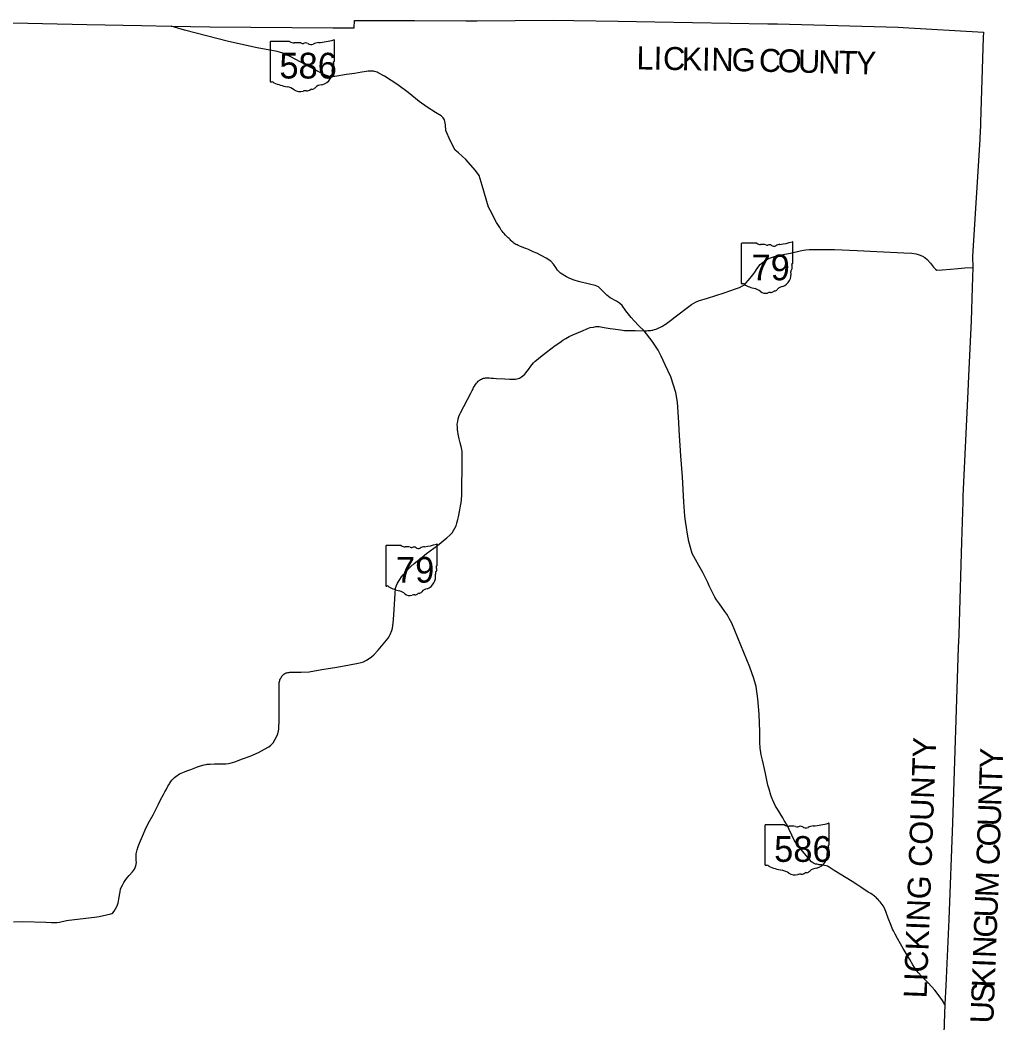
# Model space of a CAD drawing. Extents: x 1853412 to 2125412, y 679418 to 855418.
# Drawn here: x 2015090 to 2057872, y 772335 to 816009 of the extents above; entities that cross this region are included whole.
import ezdxf

# ---------------------------------------------------------------- set-up
doc = ezdxf.new("R2010")
doc.units = 0
for name, color, linetype in [('GM_X_County', 7, 'Continuous'), ('GM_X_County_Text', 7, 'Continuous'), ('GM_X_State_Location', 7, 'Continuous'), ('GM_X_State_Route', 7, 'Continuous'), ('GM_X_State_Shield', 7, 'Continuous')]:
    doc.layers.add(name, color=color, linetype=linetype)

msp = doc.modelspace()

# ---------------------------------------------------------------- linework, layer by layer
at = {"layer": 'GM_X_County'}
msp.add_lwpolyline([(2014115, 815904), (2017998, 815808), (2020382, 815768), (2021673, 815746), (2023355, 815717), (2028708, 815664), (2029367, 815674), (2029630, 815668), (2029642, 815987), (2032252, 815993), (2034492, 815973), (2034983, 815969), (2038297, 816009), (2039196, 815994), (2041129, 815964), (2042723, 815938), (2047645, 815846), (2048065, 815838), (2053316, 815692), (2053523, 815687), (2057031, 815485), (2057019, 815250), (2056899, 811568), (2056897, 811400), (2056861, 810899), (2056861, 810876), (2056863, 810840), (2056867, 810805), (2056541, 805722), (2056567, 805237), (2056538, 804363), (2056484, 802909), (2056380, 800498), (2056351, 799840), (2056130, 795281), (2056125, 795083), (2056131, 795035), (2056068, 793283), (2055973, 789772), (2055957, 789237), (2055919, 788685), (2055674, 781043), (2055513, 776843), (2055388, 773963), (2055343, 773147), (2055023, 763820)], dxfattribs=at)
at = {"layer": 'GM_X_State_Route'}
for points in [[(2029654, 813686), (2029302, 813633), (2028789, 813552), (2028645, 813551), (2028515, 813560), (2028381, 813609), (2028126, 813739), (2027312, 814168), (2026847, 814423), (2026534, 814571), (2026283, 814638), (2025407, 814794), (2024156, 815073), (2022247, 815574), (2021674, 815743)], [(2046067, 789739), (2045962, 789941), (2045911, 790035), (2045852, 790135), (2045772, 790255), (2045534, 790586), (2045403, 790755), (2045335, 790870), (2045246, 791045), (2045088, 791370), (2045024, 791509), (2044809, 791947), (2044629, 792250), (2044344, 792785), (2044203, 793304), (2044137, 793614), (2044092, 793908), (2044057, 794188), (2044031, 794403), (2043985, 795011), (2043927, 796116), (2043856, 797033), (2043783, 798155), (2043764, 798487), (2043700, 799371), (2043637, 799784), (2043413, 800466), (2043167, 801000), (2042996, 801365), (2042862, 801635), (2042599, 802028), (2042258, 802474), (2042021, 802691), (2041816, 802905), (2041692, 803051), (2041456, 803345), (2041293, 803579), (2041189, 803673), (2041048, 803761), (2040783, 803909), (2040632, 804030), (2040354, 804308), (2040267, 804394), (2040116, 804455), (2039873, 804513), (2039404, 804623), (2039204, 804675), (2039026, 804758), (2038880, 804823), (2038621, 804990), (2038489, 805117), (2038405, 805228), (2038314, 805373), (2038192, 805506), (2037995, 805646), (2037588, 805856), (2037420, 805914), (2037310, 805968), (2037219, 806010), (2037143, 806046), (2037055, 806079), (2036941, 806125), (2036843, 806162), (2036776, 806191), (2036722, 806216), (2036672, 806241), (2036631, 806265), (2036588, 806290), (2036550, 806322), (2036488, 806375), (2036459, 806404), (2036416, 806447), (2036374, 806490), (2036340, 806532), (2036268, 806599), (2036225, 806642), (2036166, 806707), (2036119, 806758), (2036077, 806810), (2036033, 806866), (2035996, 806920), (2035967, 806971), (2035831, 807189), (2035546, 807727), (2035474, 807862), (2035199, 808805), (2035071, 809238), (2034908, 809460), (2034490, 809935), (2034177, 810221), (2034031, 810349), (2033809, 810765), (2033616, 811198), (2033604, 811450), (2033562, 811659), (2033506, 811747), (2033414, 811831), (2033171, 811987), (2032809, 812211), (2032455, 812459), (2031990, 812857), (2031540, 813195), (2030955, 813563), (2030673, 813714), (2030634, 813735), (2030581, 813755), (2030522, 813772), (2030481, 813781), (2030432, 813784), (2030366, 813787), (2030311, 813783), (2030246, 813777), (2030160, 813764), (2030070, 813750), (2029959, 813734), (2029654, 813686)], [(2043160, 802748), (2043164, 802752), (2043454, 802969), (2043549, 803040), (2044314, 803625), (2044412, 803680), (2044524, 803742), (2044623, 803784), (2045008, 803904), (2045734, 804132), (2046225, 804304), (2046407, 804368), (2046537, 804434), (2046617, 804484), (2046683, 804550), (2046787, 804663), (2046872, 804772), (2047037, 804982), (2047202, 805232), (2047300, 805357), (2047452, 805484), (2047618, 805593), (2047688, 805621), (2047759, 805655), (2047929, 805709), (2048217, 805781), (2048630, 805859), (2049051, 805960), (2049195, 805984), (2049290, 805996), (2049438, 806010), (2049872, 806014), (2050540, 806010), (2051529, 805968), (2052383, 805923), (2053556, 805872), (2053908, 805854), (2054094, 805823), (2054228, 805785), (2054346, 805741), (2054479, 805665), (2054579, 805585), (2054719, 805425), (2054857, 805253), (2054942, 805160), (2054996, 805120), (2055223, 805130), (2055592, 805161), (2055927, 805188), (2056211, 805220), (2056568, 805235)], [(2031434, 791274), (2031481, 791391), (2031524, 791491), (2031618, 791652), (2031692, 791758), (2031764, 791852), (2031877, 791974), (2031981, 792090), (2032095, 792209), (2032248, 792341), (2032499, 792540), (2032787, 792772), (2033267, 793121), (2033669, 793462), (2033799, 793575), (2033893, 793674), (2033962, 793782), (2034021, 793881), (2034067, 793977), (2034104, 794100), (2034149, 794252), (2034179, 794378), (2034234, 794676), (2034266, 794847), (2034288, 794978), (2034304, 795109), (2034315, 795326), (2034321, 795678), (2034336, 796512), (2034339, 796965), (2034333, 797152), (2034328, 797223), (2034316, 797314), (2034288, 797441), (2034242, 797599), (2034202, 797776), (2034159, 797972), (2034140, 798085), (2034131, 798161), (2034126, 798263), (2034119, 798404), (2034140, 798523), (2034164, 798637), (2034193, 798738), (2034233, 798847), (2034259, 798899), (2034705, 799762), (2034764, 799873), (2034807, 799956), (2034834, 800008), (2034866, 800065), (2034913, 800142), (2034958, 800203), (2034995, 800244), (2035029, 800276), (2035060, 800303), (2035089, 800324), (2035129, 800351), (2035180, 800377), (2035218, 800393), (2035258, 800407), (2035304, 800418), (2035343, 800424), (2035387, 800428), (2035437, 800430), (2035529, 800423), (2035600, 800419), (2035691, 800412), (2035833, 800397), (2036192, 800380), (2036404, 800370), (2036648, 800370), (2036732, 800383), (2036823, 800420), (2036911, 800465), (2036973, 800508), (2037060, 800583), (2037111, 800646), (2037220, 800786), (2037322, 800938), (2037435, 801079), (2037514, 801154), (2037572, 801204), (2037742, 801346), (2038002, 801545), (2038385, 801832), (2038580, 801972), (2038719, 802066), (2038840, 802145), (2038998, 802233), (2039156, 802299), (2039325, 802375), (2039499, 802451), (2039827, 802593), (2039903, 802613), (2040054, 802640), (2040149, 802657), (2040219, 802662), (2040300, 802660), (2040521, 802627), (2040770, 802580), (2040903, 802562), (2041226, 802512), (2041406, 802495), (2041590, 802486), (2041863, 802489), (2042258, 802474), (2042359, 802480), (2042419, 802485), (2042537, 802493), (2042583, 802500), (2042635, 802511), (2042707, 802530), (2042771, 802552), (2042866, 802586), (2042968, 802631), (2043053, 802675), (2043115, 802716), (2043160, 802748)], [(2031111, 789095), (2031166, 789188), (2031202, 789252), (2031274, 789427), (2031303, 789527), (2031332, 789740), (2031350, 789909), (2031373, 790324), (2031412, 791042), (2031434, 791274)], [(2047305, 784302), (2047294, 784563), (2047287, 784832), (2047286, 785010), (2047267, 785785), (2047198, 786451), (2047128, 786989), (2047036, 787341), (2046852, 787829), (2046067, 789739)], [(2022739, 783462), (2022763, 783472), (2022937, 783529), (2023097, 783573), (2023188, 783591), (2023239, 783601), (2023366, 783610), (2023560, 783614), (2023847, 783617), (2024051, 783620), (2024168, 783630), (2024240, 783642), (2024439, 783701), (2024772, 783836), (2025099, 783956), (2025469, 784109), (2025731, 784251), (2025919, 784366), (2026006, 784438), (2026061, 784496), (2026100, 784540), (2026193, 784694), (2026247, 784789), (2026304, 784928), (2026332, 785055), (2026347, 785134), (2026360, 785239), (2026364, 785430), (2026364, 786533), (2026367, 787066), (2026370, 787127), (2026375, 787165), (2026382, 787207), (2026392, 787248), (2026402, 787291), (2026420, 787326), (2026441, 787367), (2026463, 787399), (2026481, 787431), (2026501, 787456), (2026523, 787477), (2026546, 787501), (2026576, 787524), (2026609, 787546), (2026637, 787560), (2026672, 787575), (2026707, 787586), (2026740, 787593), (2026784, 787602), (2026836, 787608), (2026946, 787611), (2027326, 787608), (2027672, 787630), (2028226, 787720), (2028885, 787829), (2029423, 787926), (2029806, 787996), (2029939, 788030), (2030036, 788064), (2030168, 788127), (2030249, 788176), (2030391, 788273), (2030494, 788369), (2030677, 788566), (2031043, 789006), (2031111, 789095)], [(2055344, 773144), (2055242, 773319), (2055100, 773508), (2054914, 773768), (2054781, 773913), (2054606, 774097), (2054367, 774333), (2054307, 774390), (2054191, 774512), (2054125, 774598), (2054095, 774638), (2053957, 774865), (2053814, 775097), (2053531, 775579), (2053418, 775780), (2053279, 776019), (2053181, 776198), (2053146, 776266), (2053106, 776350), (2053072, 776417), (2053051, 776469), (2052980, 776647), (2052908, 776823), (2052880, 776898), (2052774, 777194), (2052713, 777327), (2052654, 777429), (2052612, 777495), (2052577, 777546), (2052528, 777610), (2052486, 777659), (2052443, 777707), (2052404, 777745), (2052352, 777794), (2052315, 777824), (2052278, 777855), (2052221, 777896), (2052179, 777924), (2052116, 777965), (2052059, 778002), (2052006, 778033), (2051689, 778252), (2051557, 778328), (2051306, 778492), (2050532, 778979), (2050307, 779115), (2050231, 779162), (2050176, 779182), (2050112, 779198), (2049975, 779215), (2049870, 779225), (2049782, 779242), (2049714, 779254), (2049633, 779297), (2049546, 779352), (2049235, 779709), (2049073, 779905), (2048869, 780160), (2048782, 780294), (2048680, 780511), (2048569, 780766), (2048475, 780947), (2048357, 781153), (2048298, 781260), (2048059, 781642), (2047977, 781778), (2047909, 781908), (2047854, 782029), (2047827, 782094), (2047776, 782253), (2047696, 782513), (2047640, 782694), (2047534, 783200), (2047453, 783584), (2047411, 783785), (2047344, 784012), (2047328, 784105), (2047305, 784302)], [(2021753, 782967), (2021757, 782971), (2021814, 783023), (2021873, 783073), (2021921, 783110), (2021968, 783142), (2022035, 783182), (2022105, 783219), (2022242, 783275), (2022347, 783312), (2022521, 783372), (2022739, 783462)], [(2019302, 777412), (2019318, 777441), (2019335, 777484), (2019366, 777562), (2019375, 777628), (2019394, 777735), (2019441, 778048), (2019468, 778160), (2019491, 778233), (2019546, 778334), (2019605, 778448), (2019665, 778541), (2019744, 778640), (2019832, 778752), (2019979, 778919), (2020078, 779038), (2020134, 779176), (2020154, 779316), (2020149, 779407), (2020144, 779511), (2020140, 779597), (2020144, 779693), (2020154, 779762), (2020186, 779873), (2020234, 780015), (2020290, 780165), (2020376, 780368), (2020462, 780573), (2020532, 780737), (2020672, 781025), (2020879, 781403), (2020971, 781578), (2021072, 781778), (2021116, 781862), (2021208, 782044), (2021335, 782283), (2021397, 782403), (2021457, 782511), (2021528, 782645), (2021564, 782708), (2021592, 782754), (2021609, 782782), (2021653, 782846), (2021702, 782911), (2021753, 782967)], [(2014807, 776742), (2015208, 776755), (2016207, 776726), (2016462, 776716), (2016573, 776715), (2016688, 776707), (2016811, 776723), (2017111, 776799), (2017209, 776814), (2018334, 776942), (2018537, 776974), (2018852, 777039), (2019036, 777083), (2019088, 777104), (2019127, 777133), (2019188, 777208), (2019246, 777311), (2019302, 777412)]]:
    msp.add_lwpolyline(points, dxfattribs=at)
at = {"layer": 'GM_X_State_Shield'}
for p, q in [((2025975, 815045), (2025975, 813343)), ((2026823, 815074), (2026003, 815074)), ((2028777, 814226), (2028777, 815116)), ((2028777, 814226), (2028777, 814226)), ((2046483, 806257), (2046483, 804556)), ((2047161, 806286), (2046505, 806286)), ((2048724, 805439), (2048724, 806329)), ((2048724, 805439), (2048724, 805439)), ((2031685, 793121), (2031029, 793121)), ((2033248, 792273), (2033248, 793163)), ((2031007, 793091), (2031007, 791390)), ((2033248, 792273), (2033248, 792273)), ((2047511, 780930), (2047511, 779229)), ((2048359, 780959), (2047539, 780959)), ((2050313, 780111), (2050313, 781001)), ((2050313, 780112), (2050313, 780111))]:
    msp.add_line(p, q, dxfattribs=at)
for centre, radius, start, end in [((2046509, 806261), 26, 98.1301, 188.1301), ((2047318, 806484), 252, 231.6195, 271.1119), ((2047401, 805331), 904, 80.4867, 94.9883), ((2047607, 806270), 72.7, 219.7921, 297.1024), ((2047713, 806073), 151, 54.4667, 119.1411), ((2048229, 805767), 478, 97.3462, 120.7689), ((2047926, 808606), 2377, 275.8445, 288.9065), ((2048700, 806332), 25, 351.8621, 97.738), ((2047908, 806343), 182, 233.8562, 294.8282), ((2048719, 805373), 38.6, 107.944, 210.337), ((2048473, 805261), 232, 340.033, 23.6496), ((2048698, 805435), 26.7, 289.6038, 7.7341), ((2048059, 804953), 595, 292.3089, 8.9858), ((2048814, 805066), 169, 136.8065, 186.9296), ((2046509, 804552), 26.2, 171.9584, 258.3066), ((2046513, 804726), 200, 267.339, 280.6039), ((2046554, 804458), 72.1, 29.7484, 93.2717), ((2047464, 805986), 1716, 240.4129, 257.1985), ((2046952, 803792), 537, 47.1842, 75.836), ((2047533, 804449), 341, 230.7004, 286.2918), ((2047730, 803861), 280, 85.6951, 111.2099), ((2047755, 804322), 182, 268.777, 315.5493), ((2047919, 804157), 51.1, 65.7517, 132.6484), ((2047897, 804391), 192, 282.8732, 323.2771), ((2048310, 804078), 326, 94.4031, 142.5768), ((2031033, 793095), 26, 98.1301, 188.1301), ((2031842, 793318), 252, 231.6195, 271.1119), ((2032450, 795440), 2377, 275.8445, 288.9065), ((2033223, 793167), 25, 351.8621, 97.738), ((2031925, 792166), 904, 80.4867, 94.9883), ((2032130, 793104), 72.7, 219.7921, 297.1024), ((2032237, 792907), 151, 54.4667, 119.1411), ((2032432, 793177), 182, 233.8562, 294.8282), ((2032753, 792601), 478, 97.3462, 120.7689), ((2033222, 792270), 26.7, 289.6038, 7.7341), ((2032583, 791787), 595, 292.3089, 8.9858), ((2033338, 791901), 169, 136.8065, 186.9296), ((2033242, 792208), 38.6, 107.944, 210.337), ((2032997, 792095), 232, 340.033, 23.6496), ((2031033, 791387), 26.2, 171.9584, 258.3066), ((2031037, 791561), 200, 267.339, 280.6039), ((2031078, 791292), 72.1, 29.7484, 93.2717), ((2031988, 792821), 1716, 240.4129, 257.1985), ((2031476, 790626), 537, 47.1842, 75.836), ((2032057, 791284), 341, 230.7004, 286.2918), ((2032254, 790696), 280, 85.6951, 111.2099), ((2032279, 791156), 182, 268.777, 315.5493), ((2032443, 790992), 51.1, 65.7517, 132.6484), ((2032421, 791225), 192, 282.8732, 323.2771), ((2032834, 790913), 326, 94.4031, 142.5768)]:
    msp.add_arc(centre, radius, start, end, dxfattribs=at)
for centre, major_axis, start_param, end_param in [((2026007, 815048), (32.5, 0), 1.712693, 3.28349), ((2027019, 815271), (315, 0), 4.042523, 4.731795), ((2027123, 814119), (1130, 0), 1.404758, 1.657858), ((2027380, 815057), (90.8, 0), 3.836095, 5.185415), ((2027513, 814860), (189, 0), 0.950623, 2.079405), ((2027757, 815130), (227, 0), 4.081561, 5.145723), ((2028158, 814554), (598, 0), 1.699011, 2.107814), ((2027779, 817393), (2971, 0), 4.814394, 5.042369), ((2028746, 815120), (31.2, 0), 6.141152, 7.989035), ((2028770, 814161), (48.3, 0), 1.883978, 3.671073), ((2028463, 814048), (290, 0), 5.934695, 6.695948), ((2028744, 814223), (33.4, 0), 5.05454, 6.418171), ((2027945, 813740), (743, 0), 5.101752, 6.440018), ((2028889, 813854), (211, 0), 2.387724, 3.262537), ((2026008, 813340), (32.7, 0), 3.00124, 4.508301), ((2026013, 813514), (250, 0), 4.665946, 4.897461), ((2026064, 813245), (90.1, 0), 0.519207, 1.627899), ((2027201, 814774), (2146, 0), 4.195997, 4.488961), ((2026562, 812579), (671, 0), 0.823519, 1.323587), ((2027288, 813237), (426, 0), 4.026481, 4.996735), ((2027534, 812649), (350, 0), 1.495662, 1.94098), ((2027565, 813109), (227, 0), 4.691044, 5.507374), ((2027770, 812945), (63.9, 0), 1.147584, 2.315152), ((2027743, 813178), (240, 0), 4.937069, 5.64225), ((2028259, 812866), (407, 0), 1.647645, 2.488434), ((2047543, 780934), (32.5, 0), 1.712693, 3.28349), ((2048555, 781157), (315, 0), 4.042523, 4.731795), ((2048659, 780004), (1130, 0), 1.404758, 1.657858), ((2048916, 780942), (90.8, 0), 3.836095, 5.185415), ((2049049, 780746), (189, 0), 0.950623, 2.079405), ((2049694, 780440), (598, 0), 1.699011, 2.107814), ((2049315, 783278), (2971, 0), 4.814394, 5.042369), ((2050282, 781005), (31.2, 0), 6.141152, 7.989035), ((2049293, 781015), (227, 0), 4.081561, 5.145723), ((2050306, 780046), (48.3, 0), 1.883978, 3.671073), ((2049999, 779934), (290, 0), 5.934695, 6.695948), ((2050280, 780108), (33.4, 0), 5.05454, 6.418171), ((2049481, 779626), (743, 0), 5.101752, 6.440018), ((2050425, 779739), (211, 0), 2.387724, 3.262537), ((2047544, 779225), (32.7, 0), 3.00124, 4.508301), ((2047549, 779399), (250, 0), 4.665946, 4.897461), ((2047600, 779131), (90.1, 0), 0.519207, 1.627899), ((2048737, 780659), (2146, 0), 4.195997, 4.488961), ((2048098, 778464), (671, 0), 0.823519, 1.323587), ((2048824, 779122), (426, 0), 4.026481, 4.996735), ((2049070, 778534), (350, 0), 1.495662, 1.94098), ((2049101, 778995), (227, 0), 4.691044, 5.507374), ((2049306, 778830), (63.9, 0), 1.147584, 2.315152), ((2049279, 779064), (240, 0), 4.937069, 5.64225), ((2049795, 778751), (407, 0), 1.647645, 2.488434)]:
    msp.add_ellipse(centre, major_axis=major_axis, ratio=0.8, start_param=start_param, end_param=end_param, dxfattribs=at)

# ---------------------------------------------------------------- texts
at = {"layer": 'GM_X_County_Text'}
for s, rotation, p in [('L', 359.0467, (2041917, 813862)), ('I', 358.965, (2042663, 813850)), ('C', 358.9435, (2043070, 813842)), ('K', 358.9262, (2043885, 813827)), ('I', 358.9237, (2044767, 813811)), ('N', 358.9213, (2045174, 813803)), ('G', 358.8859, (2046057, 813787)), ('C', 358.7105, (2047244, 813763)), ('O', 358.6096, (2048058, 813745)), ('U', 358.4723, (2048940, 813723)), ('N', 358.4249, (2049822, 813700)), ('T', 358.4186, (2050705, 813676)), ('Y', 358.4186, (2051451, 813655)), ('LICKING COUNTY', 87.8896, (2054551, 773397)), ('Y', 88.0873, (2057855, 783401)), ('T', 88.0873, (2057831, 782654)), ('N', 88.0714, (2057801, 781772)), ('U', 88.0411, (2057771, 780889)), ('O', 88.001, (2057740, 780006)), ('C', 87.9537, (2057711, 779191)), ('M', 87.9381, (2057661, 777799)), ('U', 87.8907, (2057628, 776916)), ('G', 87.85, (2057595, 776033)), ('N', 87.8204, (2057561, 775151)), ('I', 87.807, (2057546, 774744)), ('K', 87.7997, (2057512, 773862)), ('S', 87.7976, (2057486, 773182)), ('U', 87.7975, (2057452, 772300))]:
    msp.add_text(s, height=1000, rotation=rotation, dxfattribs=at).set_placement(p)
at = {"layer": 'GM_X_State_Location'}
for s, p in [('586', (2026878, 813991)), ('79', (2047259, 805230)), ('586', (2040553, 803800)), ('79', (2031845, 792017)), ('586', (2048689, 779860)), ('79', (2015403, 776551))]:
    msp.add_text(s, height=1, rotation=0, dxfattribs=at).set_placement(p)
for s, p in [('s', (2027231, 814063)), ('r', (2027231, 814063)), ('s', (2047510, 805303)), ('r', (2047510, 805303)), ('s', (2040906, 803873)), ('r', (2040906, 803873)), ('s', (2032097, 792090)), ('r', (2032097, 792090)), ('s', (2049042, 779933)), ('r', (2049042, 779933)), ('s', (2015654, 776624)), ('r', (2015654, 776624))]:
    msp.add_text(s, height=1, dxfattribs=at).set_placement(p)
at = {"layer": 'GM_X_State_Shield'}
for s, p in [('586', (2026378, 813463)), ('79', (2046930, 804676)), ('79', (2031454, 791510)), ('586', (2047914, 779349))]:
    msp.add_text(s, height=1120.7, dxfattribs=at).set_placement(p)

doc.saveas('drawing.dxf')
